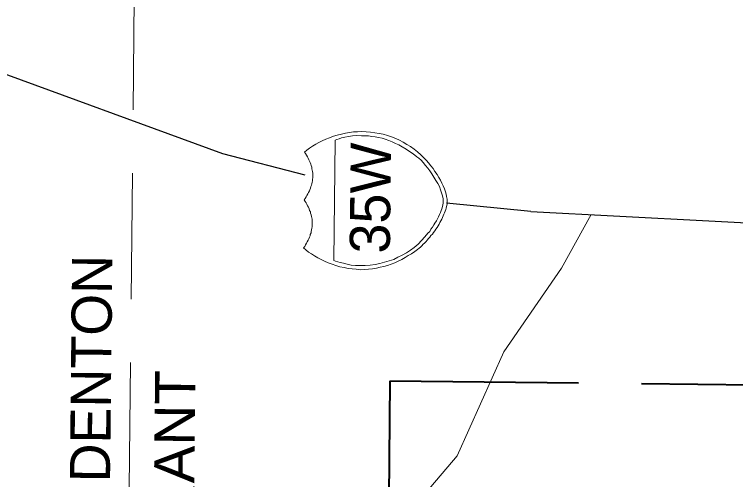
# Model space of a CAD drawing. Extents: x 2356576 to 2377878, y 6966390 to 6990634.
# Drawn here: x 2365706.5 to 2365828.3, y 6968885.6 to 6968964.1 of the extents above; entities that cross this region are included whole.
import ezdxf

# ---------------------------------------------------------------- set-up
doc = ezdxf.new("R2010")
doc.units = 0
doc.header["$LTSCALE"] = 7.1
doc.linetypes.add('LONG_DASHED', pattern=[7.5, 6, -1.5])
doc.linetypes.add('MEDIUM_DASHED', pattern=[4.5, 3, -1.5])
doc.layers.add('19', color=7, linetype='Continuous', lineweight=13)
doc.layers.add('8', color=7, linetype='Continuous', lineweight=13)

msp = doc.modelspace()

# ---------------------------------------------------------------- linework, layer by layer
at = {"layer": '19', "linetype": 'MEDIUM_DASHED'}
msp.add_line((2365729.713, 6969256.812), (2365723.521, 6968659.188), dxfattribs=at)
at = {"layer": '19', "lineweight": 25}
for p, q in [((2365741.618, 6968940.608), (2365755.529, 6968937.015)), ((2365793.72, 6968930.86), (2365779.453, 6968932.267))]:
    msp.add_line(p, q, dxfattribs=at)
for points in [[(2365600.667, 6969007.475), (2365602.216, 6969006.467), (2365640.615, 6968991.489), (2365676.135, 6968970.808), (2365700.639, 6968955.613), (2365741.618, 6968940.608)], [(2365793.72, 6968930.86), (2365853.846, 6968927.685), (2365867.731, 6968930.001)]]:
    msp.add_lwpolyline(points, dxfattribs=at)
at = {"layer": '19'}
for points in [[(2365756.008, 6968933.798), (2365756.162, 6968934.037), (2365756.285, 6968934.308), (2365756.375, 6968934.515), (2365756.498, 6968934.785), (2365756.533, 6968935.053), (2365756.655, 6968935.292), (2365756.686, 6968935.531), (2365756.749, 6968935.803), (2365756.811, 6968936.042), (2365756.846, 6968936.31), (2365756.848, 6968936.55), (2365756.851, 6968936.822), (2365756.854, 6968937.062), (2365756.856, 6968937.302), (2365756.827, 6968937.602), (2365756.77, 6968937.811), (2365756.712, 6968938.051), (2365756.687, 6968938.324), (2365756.57, 6968938.593), (2365756.54, 6968938.833), (2365756.423, 6968939.106), (2365756.337, 6968939.347), (2365756.22, 6968939.588), (2365756.07, 6968939.83), (2365755.953, 6968940.071), (2365755.808, 6968940.341), (2365755.659, 6968940.614), (2365755.481, 6968940.856), (2365755.877, 6968941.212), (2365756.328, 6968941.535), (2365756.812, 6968941.862), (2365757.355, 6968942.185), (2365757.898, 6968942.479), (2365758.473, 6968942.773), (2365759.044, 6968943.039), (2365759.679, 6968943.301), (2365760.369, 6968943.534), (2365761.003, 6968943.739), (2365761.693, 6968943.912), (2365762.387, 6968944.053), (2365763.076, 6968944.166), (2365763.737, 6968944.279), (2365764.429, 6968944.304), (2365765.118, 6968944.357), (2365765.869, 6968944.289), (2365766.617, 6968944.249), (2365767.367, 6968944.121), (2365768.055, 6968944.026), (2365768.773, 6968943.899), (2365769.491, 6968943.651), (2365770.181, 6968943.432), (2365770.866, 6968943.185), (2365771.523, 6968942.878), (2365772.151, 6968942.544), (2365772.776, 6968942.177), (2365773.372, 6968941.811), (2365773.999, 6968941.352), (2365774.562, 6968940.899), (2365775.097, 6968940.413), (2365775.664, 6968939.867), (2365776.048, 6968939.471), (2365776.435, 6968939.047), (2365776.818, 6968938.563), (2365777.174, 6968938.111), (2365777.5, 6968937.596), (2365777.855, 6968937.084), (2365778.15, 6968936.601), (2365778.413, 6968936.118), (2365778.68, 6968935.636), (2365778.915, 6968935.153), (2365779.118, 6968934.671), (2365779.265, 6968934.189), (2365779.381, 6968933.768), (2365779.465, 6968933.347), (2365779.552, 6968932.926), (2365779.548, 6968932.566)], [(2365779.548, 6968932.566), (2365779.546, 6968932.326), (2365779.544, 6968932.114), (2365779.481, 6968931.875), (2365779.447, 6968931.667), (2365779.385, 6968931.428), (2365779.322, 6968931.189), (2365779.231, 6968930.89), (2365779.136, 6968930.619), (2365779.014, 6968930.38), (2365778.891, 6968930.109), (2365778.768, 6968929.81), (2365778.645, 6968929.544), (2365778.494, 6968929.245), (2365778.34, 6968929.007), (2365778.188, 6968928.708), (2365778.033, 6968928.41), (2365777.851, 6968928.14), (2365777.639, 6968927.842), (2365777.457, 6968927.576), (2365777.242, 6968927.306), (2365777.059, 6968927.04), (2365776.816, 6968926.77), (2365776.633, 6968926.504), (2365776.423, 6968926.266), (2365776.208, 6968925.997), (2365775.998, 6968925.759), (2365775.755, 6968925.521), (2365775.513, 6968925.316), (2365775.298, 6968925.046), (2365775.056, 6968924.841), (2365774.846, 6968924.663), (2365774.572, 6968924.454), (2365774.088, 6968924.099), (2365773.544, 6968923.716), (2365772.973, 6968923.39), (2365772.458, 6968923.067), (2365771.886, 6968922.741), (2365771.311, 6968922.447), (2365770.708, 6968922.185), (2365770.106, 6968921.98), (2365769.504, 6968921.746), (2365768.874, 6968921.572), (2365768.24, 6968921.431), (2365767.611, 6968921.285), (2365766.949, 6968921.144), (2365766.289, 6968921.091), (2365765.568, 6968921.039), (2365764.876, 6968921.014), (2365764.189, 6968921.081), (2365763.497, 6968921.148), (2365762.838, 6968921.247), (2365762.152, 6968921.374), (2365761.461, 6968921.529), (2365760.775, 6968921.716), (2365760.145, 6968921.935), (2365759.459, 6968922.15), (2365758.831, 6968922.456), (2365758.265, 6968922.734), (2365757.697, 6968923.04), (2365757.16, 6968923.346), (2365756.623, 6968923.711), (2365756.146, 6968923.984), (2365755.702, 6968924.349), (2365755.314, 6968924.713), (2365755.496, 6968924.951), (2365755.651, 6968925.222), (2365755.802, 6968925.488), (2365755.924, 6968925.727), (2365756.079, 6968925.997), (2365756.202, 6968926.236), (2365756.292, 6968926.503), (2365756.415, 6968926.742), (2365756.449, 6968926.981), (2365756.572, 6968927.22), (2365756.603, 6968927.492), (2365756.665, 6968927.731), (2365756.728, 6968928.031), (2365756.762, 6968928.238), (2365756.765, 6968928.478), (2365756.768, 6968928.778), (2365756.77, 6968929.018), (2365756.773, 6968929.258), (2365756.744, 6968929.53), (2365756.686, 6968929.771), (2365756.629, 6968930.012), (2365756.603, 6968930.252), (2365756.486, 6968930.553), (2365756.457, 6968930.794), (2365756.339, 6968931.035), (2365756.254, 6968931.276), (2365756.137, 6968931.549), (2365755.987, 6968931.818), (2365755.87, 6968932.06), (2365755.724, 6968932.301), (2365755.575, 6968932.543), (2365755.398, 6968932.817), (2365755.58, 6968933.055), (2365755.735, 6968933.293), (2365755.885, 6968933.56), (2365756.008, 6968933.798)], [(2365764.43, 6968869.084), (2365766.717, 6968869.78), (2365772.031, 6968878.757), (2365781.232, 6968889.615), (2365789.126, 6968907.142), (2365798.873, 6968921.294), (2365803.859, 6968930.334)]]:
    msp.add_lwpolyline(points, dxfattribs=at)
msp.add_lwpolyline([(2365760.635, 6968942.903), (2365760.424, 6968922.592), (2365760.723, 6968922.469), (2365761.082, 6968922.345), (2365761.5, 6968922.221), (2365762.067, 6968922.095), (2365762.665, 6968921.937), (2365763.324, 6968921.81), (2365764.075, 6968921.742), (2365764.883, 6968921.734), (2365765.723, 6968921.725), (2365766.564, 6968921.776), (2365767.405, 6968921.888), (2365768.187, 6968922.06), (2365769.001, 6968922.263), (2365769.752, 6968922.495), (2365770.534, 6968922.755), (2365771.258, 6968923.108), (2365771.954, 6968923.461), (2365772.678, 6968923.845), (2365773.343, 6968924.318), (2365774.008, 6968924.791), (2365774.641, 6968925.353), (2365775.22, 6968925.947), (2365775.794, 6968926.541), (2365776.313, 6968927.196), (2365776.616, 6968927.493), (2365776.827, 6968927.85), (2365777.071, 6968928.18), (2365777.287, 6968928.566), (2365777.498, 6968928.895), (2365777.742, 6968929.253), (2365777.926, 6968929.611), (2365778.109, 6968929.969), (2365778.265, 6968930.328), (2365778.417, 6968930.658), (2365778.572, 6968931.016), (2365778.663, 6968931.316), (2365778.759, 6968931.675), (2365778.822, 6968931.974), (2365778.885, 6968932.273), (2365778.888, 6968932.573), (2365778.861, 6968932.994), (2365778.778, 6968933.502), (2365778.631, 6968933.984), (2365778.429, 6968934.526), (2365778.254, 6968935.04), (2365777.96, 6968935.583), (2365777.665, 6968936.094), (2365777.339, 6968936.638), (2365776.984, 6968937.181), (2365776.629, 6968937.697), (2365776.274, 6968938.181), (2365775.891, 6968938.633), (2365775.536, 6968939.088), (2365775.148, 6968939.48), (2365774.792, 6968939.844), (2365774.434, 6968940.088), (2365773.839, 6968940.574), (2365773.215, 6968940.972), (2365772.647, 6968941.366), (2365771.991, 6968941.733), (2365771.426, 6968942.071), (2365770.857, 6968942.345), (2365770.292, 6968942.591), (2365769.694, 6968942.809), (2365769.096, 6968943.023), (2365768.558, 6968943.209), (2365767.959, 6968943.335), (2365767.388, 6968943.433), (2365766.821, 6968943.527), (2365766.25, 6968943.593), (2365765.682, 6968943.631), (2365765.11, 6968943.637), (2365764.302, 6968943.645), (2365763.55, 6968943.593), (2365762.889, 6968943.48), (2365762.288, 6968943.394), (2365761.718, 6968943.252), (2365761.297, 6968943.104), (2365760.935, 6968942.988)], close=True, dxfattribs=at)
at = {"layer": '19', "linetype": 'LONG_DASHED', "lineweight": 40}
msp.add_lwpolyline([(2365767.5, 6968670.405), (2365852.579, 6968669.524), (2365854.981, 6968901.299), (2365769.901, 6968902.181), (2365767.496, 6968669.985)], dxfattribs=at)
at = {"layer": '8', "linetype": 'MEDIUM_DASHED'}
msp.add_line((2365729.713, 6969256.812), (2365723.521, 6968659.188), dxfattribs=at)
at = {"layer": '8', "lineweight": 25}
for p, q in [((2365741.618, 6968940.608), (2365755.529, 6968937.015)), ((2365793.72, 6968930.86), (2365779.453, 6968932.267))]:
    msp.add_line(p, q, dxfattribs=at)
for points in [[(2365600.667, 6969007.475), (2365602.216, 6969006.467), (2365640.615, 6968991.489), (2365676.135, 6968970.808), (2365700.639, 6968955.613), (2365741.618, 6968940.608)], [(2365793.72, 6968930.86), (2365853.846, 6968927.685), (2365867.731, 6968930.001)]]:
    msp.add_lwpolyline(points, dxfattribs=at)
at = {"layer": '8'}
for points in [[(2365756.008, 6968933.798), (2365756.162, 6968934.037), (2365756.285, 6968934.308), (2365756.375, 6968934.515), (2365756.498, 6968934.785), (2365756.533, 6968935.053), (2365756.655, 6968935.292), (2365756.686, 6968935.531), (2365756.749, 6968935.803), (2365756.811, 6968936.042), (2365756.846, 6968936.31), (2365756.848, 6968936.55), (2365756.851, 6968936.822), (2365756.854, 6968937.062), (2365756.856, 6968937.302), (2365756.827, 6968937.602), (2365756.77, 6968937.811), (2365756.712, 6968938.051), (2365756.687, 6968938.324), (2365756.57, 6968938.593), (2365756.54, 6968938.833), (2365756.423, 6968939.106), (2365756.337, 6968939.347), (2365756.22, 6968939.588), (2365756.07, 6968939.83), (2365755.953, 6968940.071), (2365755.808, 6968940.341), (2365755.659, 6968940.614), (2365755.481, 6968940.856), (2365755.877, 6968941.212), (2365756.328, 6968941.535), (2365756.812, 6968941.862), (2365757.355, 6968942.185), (2365757.898, 6968942.479), (2365758.473, 6968942.773), (2365759.044, 6968943.039), (2365759.679, 6968943.301), (2365760.369, 6968943.534), (2365761.003, 6968943.739), (2365761.693, 6968943.912), (2365762.387, 6968944.053), (2365763.076, 6968944.166), (2365763.737, 6968944.279), (2365764.429, 6968944.304), (2365765.118, 6968944.357), (2365765.869, 6968944.289), (2365766.617, 6968944.249), (2365767.367, 6968944.121), (2365768.055, 6968944.026), (2365768.773, 6968943.899), (2365769.491, 6968943.651), (2365770.181, 6968943.432), (2365770.866, 6968943.185), (2365771.523, 6968942.878), (2365772.151, 6968942.544), (2365772.776, 6968942.177), (2365773.372, 6968941.811), (2365773.999, 6968941.352), (2365774.562, 6968940.899), (2365775.097, 6968940.413), (2365775.664, 6968939.867), (2365776.048, 6968939.471), (2365776.435, 6968939.047), (2365776.818, 6968938.563), (2365777.174, 6968938.111), (2365777.5, 6968937.596), (2365777.855, 6968937.084), (2365778.15, 6968936.601), (2365778.413, 6968936.118), (2365778.68, 6968935.636), (2365778.915, 6968935.153), (2365779.118, 6968934.671), (2365779.265, 6968934.189), (2365779.381, 6968933.768), (2365779.465, 6968933.347), (2365779.552, 6968932.926), (2365779.548, 6968932.566)], [(2365779.548, 6968932.566), (2365779.546, 6968932.326), (2365779.544, 6968932.114), (2365779.481, 6968931.875), (2365779.447, 6968931.667), (2365779.385, 6968931.428), (2365779.322, 6968931.189), (2365779.231, 6968930.89), (2365779.136, 6968930.619), (2365779.014, 6968930.38), (2365778.891, 6968930.109), (2365778.768, 6968929.81), (2365778.645, 6968929.544), (2365778.494, 6968929.245), (2365778.34, 6968929.007), (2365778.188, 6968928.708), (2365778.033, 6968928.41), (2365777.851, 6968928.14), (2365777.639, 6968927.842), (2365777.457, 6968927.576), (2365777.242, 6968927.306), (2365777.059, 6968927.04), (2365776.816, 6968926.77), (2365776.633, 6968926.504), (2365776.423, 6968926.266), (2365776.208, 6968925.997), (2365775.998, 6968925.759), (2365775.755, 6968925.521), (2365775.513, 6968925.316), (2365775.298, 6968925.046), (2365775.056, 6968924.841), (2365774.846, 6968924.663), (2365774.572, 6968924.454), (2365774.088, 6968924.099), (2365773.544, 6968923.716), (2365772.973, 6968923.39), (2365772.458, 6968923.067), (2365771.886, 6968922.741), (2365771.311, 6968922.447), (2365770.708, 6968922.185), (2365770.106, 6968921.98), (2365769.504, 6968921.746), (2365768.874, 6968921.572), (2365768.24, 6968921.431), (2365767.611, 6968921.285), (2365766.949, 6968921.144), (2365766.289, 6968921.091), (2365765.568, 6968921.039), (2365764.876, 6968921.014), (2365764.189, 6968921.081), (2365763.497, 6968921.148), (2365762.838, 6968921.247), (2365762.152, 6968921.374), (2365761.461, 6968921.529), (2365760.775, 6968921.716), (2365760.145, 6968921.935), (2365759.459, 6968922.15), (2365758.831, 6968922.456), (2365758.265, 6968922.734), (2365757.697, 6968923.04), (2365757.16, 6968923.346), (2365756.623, 6968923.711), (2365756.146, 6968923.984), (2365755.702, 6968924.349), (2365755.314, 6968924.713), (2365755.496, 6968924.951), (2365755.651, 6968925.222), (2365755.802, 6968925.488), (2365755.924, 6968925.727), (2365756.079, 6968925.997), (2365756.202, 6968926.236), (2365756.292, 6968926.503), (2365756.415, 6968926.742), (2365756.449, 6968926.981), (2365756.572, 6968927.22), (2365756.603, 6968927.492), (2365756.665, 6968927.731), (2365756.728, 6968928.031), (2365756.762, 6968928.238), (2365756.765, 6968928.478), (2365756.768, 6968928.778), (2365756.77, 6968929.018), (2365756.773, 6968929.258), (2365756.744, 6968929.53), (2365756.686, 6968929.771), (2365756.629, 6968930.012), (2365756.603, 6968930.252), (2365756.486, 6968930.553), (2365756.457, 6968930.794), (2365756.339, 6968931.035), (2365756.254, 6968931.276), (2365756.137, 6968931.549), (2365755.987, 6968931.818), (2365755.87, 6968932.06), (2365755.724, 6968932.301), (2365755.575, 6968932.543), (2365755.398, 6968932.817), (2365755.58, 6968933.055), (2365755.735, 6968933.293), (2365755.885, 6968933.56), (2365756.008, 6968933.798)], [(2365764.43, 6968869.084), (2365766.717, 6968869.78), (2365772.031, 6968878.757), (2365781.232, 6968889.615), (2365789.126, 6968907.142), (2365798.873, 6968921.294), (2365803.859, 6968930.334)]]:
    msp.add_lwpolyline(points, dxfattribs=at)
msp.add_lwpolyline([(2365760.635, 6968942.903), (2365760.424, 6968922.592), (2365760.723, 6968922.469), (2365761.082, 6968922.345), (2365761.5, 6968922.221), (2365762.067, 6968922.095), (2365762.665, 6968921.937), (2365763.324, 6968921.81), (2365764.075, 6968921.742), (2365764.883, 6968921.734), (2365765.723, 6968921.725), (2365766.564, 6968921.776), (2365767.405, 6968921.888), (2365768.187, 6968922.06), (2365769.001, 6968922.263), (2365769.752, 6968922.495), (2365770.534, 6968922.755), (2365771.258, 6968923.108), (2365771.954, 6968923.461), (2365772.678, 6968923.845), (2365773.343, 6968924.318), (2365774.008, 6968924.791), (2365774.641, 6968925.353), (2365775.22, 6968925.947), (2365775.794, 6968926.541), (2365776.313, 6968927.196), (2365776.616, 6968927.493), (2365776.827, 6968927.85), (2365777.071, 6968928.18), (2365777.287, 6968928.566), (2365777.498, 6968928.895), (2365777.742, 6968929.253), (2365777.926, 6968929.611), (2365778.109, 6968929.969), (2365778.265, 6968930.328), (2365778.417, 6968930.658), (2365778.572, 6968931.016), (2365778.663, 6968931.316), (2365778.759, 6968931.675), (2365778.822, 6968931.974), (2365778.885, 6968932.273), (2365778.888, 6968932.573), (2365778.861, 6968932.994), (2365778.778, 6968933.502), (2365778.631, 6968933.984), (2365778.429, 6968934.526), (2365778.254, 6968935.04), (2365777.96, 6968935.583), (2365777.665, 6968936.094), (2365777.339, 6968936.638), (2365776.984, 6968937.181), (2365776.629, 6968937.697), (2365776.274, 6968938.181), (2365775.891, 6968938.633), (2365775.536, 6968939.088), (2365775.148, 6968939.48), (2365774.792, 6968939.844), (2365774.434, 6968940.088), (2365773.839, 6968940.574), (2365773.215, 6968940.972), (2365772.647, 6968941.366), (2365771.991, 6968941.733), (2365771.426, 6968942.071), (2365770.857, 6968942.345), (2365770.292, 6968942.591), (2365769.694, 6968942.809), (2365769.096, 6968943.023), (2365768.558, 6968943.209), (2365767.959, 6968943.335), (2365767.388, 6968943.433), (2365766.821, 6968943.527), (2365766.25, 6968943.593), (2365765.682, 6968943.631), (2365765.11, 6968943.637), (2365764.302, 6968943.645), (2365763.55, 6968943.593), (2365762.889, 6968943.48), (2365762.288, 6968943.394), (2365761.718, 6968943.252), (2365761.297, 6968943.104), (2365760.935, 6968942.988)], close=True, dxfattribs=at)
at = {"layer": '8', "linetype": 'LONG_DASHED', "lineweight": 40}
msp.add_lwpolyline([(2365767.5, 6968670.405), (2365852.579, 6968669.524), (2365854.981, 6968901.299), (2365769.901, 6968902.181), (2365767.496, 6968669.985)], dxfattribs=at)

# ---------------------------------------------------------------- texts
at = {"layer": '19'}
for s, p in [('35W', (2365769.884, 6968923.722)), ('DENTON', (2365722.622, 6968885.09))]:
    msp.add_text(s, height=6.798, rotation=89.406, dxfattribs=at).set_placement(p)
at = {"layer": '19', "width": 1.05}
msp.add_text('TARRANT', height=6.798, rotation=89.406, dxfattribs=at).set_placement((2365736.572, 6968858.964))
at = {"layer": '8'}
for s, p in [('35W', (2365769.884, 6968923.722)), ('DENTON', (2365722.622, 6968885.09))]:
    msp.add_text(s, height=6.798, rotation=89.406, dxfattribs=at).set_placement(p)
at = {"layer": '8', "width": 1.05}
msp.add_text('TARRANT', height=6.798, rotation=89.406, dxfattribs=at).set_placement((2365736.572, 6968858.964))

doc.saveas('drawing.dxf')
